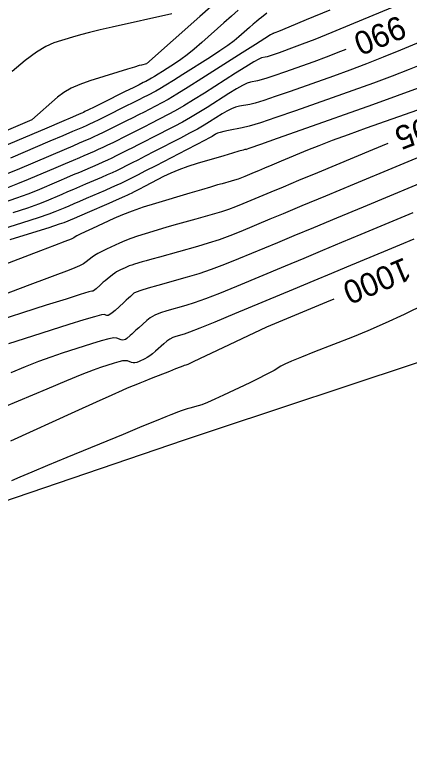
# Model space of a CAD drawing. Extents: x 2175772 to 2185556, y 721391 to 722853.
# Drawn here: x 2178722.5 to 2178770, y 721747 to 721837.5 of the extents above; entities that cross this region are included whole.
import ezdxf

# ---------------------------------------------------------------- set-up
doc = ezdxf.new("R2010")
doc.units = 0
for name, color, linetype in [('DT_X_Contour_Major', 7, 'Continuous'), ('DT_X_Contour_Minor', 7, 'Continuous'), ('DT_X_TIN_Hull', 7, 'Continuous'), ('SV_X_Break_Lines', 7, 'Continuous')]:
    doc.layers.add(name, color=color, linetype=linetype)

msp = doc.modelspace()

# ---------------------------------------------------------------- linework, layer by layer
at = {"layer": 'DT_X_Contour_Major'}
for points in [[(2178746.032, 721838.529), (2178744.732, 721837.385), (2178738.312, 721831.671), (2178737.684, 721831.532), (2178737.408, 721831.456), (2178736.847, 721831.288), (2178736.001, 721831.029), (2178734.872, 721830.678), (2178731.481, 721829.619), (2178730.285, 721829.199), (2178729.24, 721828.732), (2178728.348, 721828.218), (2178727.607, 721827.658), (2178724.501, 721824.937), (2178718.004, 721822.167)], [(2178762.304, 721833.408), (2178761.656, 721833.148), (2178759.901, 721832.468), (2178758.437, 721831.93), (2178754.921, 721830.685), (2178753.729, 721830.269), (2178752.787, 721829.955), (2178752.097, 721829.743), (2178751.659, 721829.633), (2178750.823, 721829.475), (2178750.426, 721829.345), (2178749.859, 721829.072), (2178749.124, 721828.657), (2178748.22, 721828.099), (2178745.584, 721826.422), (2178744.596, 721825.808), (2178743.61, 721825.225), (2178742.626, 721824.673), (2178741.643, 721824.151), (2178739.024, 721822.801), (2178738.101, 721822.326), (2178737.295, 721821.914), (2178736.606, 721821.564), (2178736.035, 721821.277), (2178734.668, 721820.596), (2178734.145, 721820.34), (2178733.602, 721820.085), (2178733.039, 721819.829), (2178732.456, 721819.574), (2178730.875, 721818.892), (2178730.234, 721818.617), (2178729.498, 721818.302), (2178728.668, 721817.947), (2178727.742, 721817.552), (2178725.147, 721816.445), (2178724.044, 721816.004), (2178722.68, 721815.508), (2178721.057, 721814.959)], [(2178767.335, 721822.079), (2178765.507, 721821.326), (2178758.887, 721818.571), (2178756.607, 721817.621), (2178754.732, 721816.84), (2178753.261, 721816.228), (2178749.891, 721814.822), (2178749.03, 721814.477), (2178748.173, 721814.163), (2178747.321, 721813.881), (2178746.474, 721813.63), (2178744.221, 721813.002), (2178743.364, 721812.761), (2178742.482, 721812.508), (2178741.575, 721812.243), (2178740.643, 721811.967), (2178738.125, 721811.215), (2178737.224, 721810.934), (2178736.412, 721810.655), (2178735.689, 721810.379), (2178735.053, 721810.104), (2178733.477, 721809.375), (2178732.926, 721809.109), (2178732.456, 721808.859), (2178732.066, 721808.624), (2178731.757, 721808.404), (2178731.042, 721807.838), (2178730.711, 721807.616), (2178730.258, 721807.376), (2178729.681, 721807.116), (2178728.981, 721806.838), (2178726.948, 721806.071), (2178725.976, 721805.705), (2178724.582, 721805.183), (2178722.766, 721804.504), (2178720.53, 721803.669)], [(2178760.824, 721803.359), (2178759.973, 721803.004), (2178752.737, 721799.984), (2178746.039, 721796.804), (2178744.775, 721796.205), (2178743.852, 721795.773), (2178743.272, 721795.506), (2178743.033, 721795.406), (2178742.853, 721795.359), (2178742.69, 721795.302), (2178742.338, 721795.169), (2178741.796, 721794.959), (2178741.064, 721794.671), (2178738.86, 721793.802), (2178738.104, 721793.503), (2178737.49, 721793.259), (2178737.016, 721793.07), (2178736.684, 721792.935), (2178735.986, 721792.647), (2178735.395, 721792.388), (2178734.147, 721791.826), (2178732.239, 721790.962), (2178729.674, 721789.794), (2178721.955, 721786.277)]]:
    msp.add_lwpolyline(points, dxfattribs=at)
at = {"layer": 'DT_X_Contour_Minor'}
for points in [[(2178770.884, 721839.73), (2178763.209, 721836.537), (2178760.606, 721835.459), (2178758.551, 721834.62), (2178757.045, 721834.02), (2178756.089, 721833.659), (2178754.27, 721833.015), (2178753.653, 721832.799), (2178753.166, 721832.637), (2178752.809, 721832.527), (2178752.582, 721832.47), (2178752.15, 721832.389), (2178751.833, 721832.25), (2178751.205, 721831.896), (2178750.267, 721831.327), (2178749.019, 721830.541), (2178745.275, 721828.159), (2178743.949, 721827.327), (2178742.779, 721826.618), (2178741.764, 721826.031), (2178740.904, 721825.567), (2178738.82, 721824.492), (2178738.055, 721824.099), (2178737.324, 721823.726), (2178736.626, 721823.374), (2178735.963, 721823.041), (2178734.238, 721822.182), (2178733.615, 721821.875), (2178733.037, 721821.598), (2178732.505, 721821.353), (2178732.019, 721821.138), (2178730.784, 721820.606), (2178730.224, 721820.365), (2178729.47, 721820.043), (2178728.523, 721819.638), (2178727.382, 721819.151), (2178724.08, 721817.744), (2178722.789, 721817.217), (2178721.391, 721816.692)], [(2178749.324, 721838.112), (2178748.516, 721837.418), (2178747.589, 721836.601), (2178744.958, 721834.26), (2178744.021, 721833.444), (2178743.183, 721832.755), (2178742.444, 721832.191), (2178741.805, 721831.753), (2178740.231, 721830.751), (2178739.692, 721830.411), (2178739.255, 721830.141), (2178738.921, 721829.942), (2178738.689, 721829.813), (2178738.206, 721829.564), (2178737.916, 721829.417), (2178737.41, 721829.163), (2178736.687, 721828.801), (2178735.746, 721828.332), (2178732.95, 721826.938), (2178732.023, 721826.477), (2178731.34, 721826.139), (2178730.901, 721825.923), (2178730.706, 721825.83), (2178730.511, 721825.746), (2178730.193, 721825.61), (2178729.385, 721825.266), (2178728.088, 721824.712), (2178726.3, 721823.95), (2178720.88, 721821.64)], [(2178760.379, 721838.144), (2178757.509, 721836.95), (2178755.446, 721836.093), (2178754.19, 721835.572), (2178753.741, 721835.388), (2178753.619, 721835.344), (2178753.577, 721835.33), (2178753.545, 721835.319), (2178753.521, 721835.312), (2178753.506, 721835.308), (2178753.476, 721835.302), (2178753.24, 721835.156), (2178752.551, 721834.72), (2178751.41, 721833.996), (2178749.817, 721832.983), (2178744.967, 721829.897), (2178743.302, 721828.847), (2178741.948, 721828.011), (2178740.902, 721827.389), (2178740.166, 721826.982), (2178738.615, 721826.183), (2178738.009, 721825.872), (2178737.353, 721825.538), (2178736.646, 721825.183), (2178735.891, 721824.805), (2178733.809, 721823.767), (2178733.084, 721823.409), (2178732.471, 721823.112), (2178731.97, 721822.876), (2178731.581, 721822.702), (2178730.693, 721822.319), (2178730.214, 721822.114), (2178729.442, 721821.784), (2178728.378, 721821.329), (2178723.014, 721819.043), (2178721.534, 721818.431)], [(2178752.788, 721837.751), (2178752.133, 721837.254), (2178751.859, 721837.038), (2178751.527, 721836.763), (2178751.139, 721836.429), (2178750.692, 721836.036), (2178749.426, 721834.909), (2178748.855, 721834.441), (2178748.092, 721833.88), (2178747.137, 721833.227), (2178745.99, 721832.482), (2178742.676, 721830.373), (2178741.54, 721829.656), (2178740.621, 721829.088), (2178739.916, 721828.669), (2178739.427, 721828.398), (2178738.411, 721827.874), (2178737.963, 721827.645), (2178737.381, 721827.351), (2178736.667, 721826.992), (2178735.819, 721826.569), (2178733.379, 721825.353), (2178732.553, 721824.943), (2178731.906, 721824.625), (2178731.436, 721824.4), (2178731.144, 721824.266), (2178730.602, 721824.033), (2178730.203, 721823.862), (2178729.414, 721823.525), (2178728.233, 721823.021), (2178726.661, 721822.351), (2178721.947, 721820.341)], [(2178741.339, 721837.692), (2178734.175, 721836.1), (2178732.726, 721835.768), (2178731.45, 721835.456), (2178730.345, 721835.163), (2178729.412, 721834.889), (2178727.154, 721834.184), (2178726.207, 721833.772), (2178725.059, 721833.064), (2178723.709, 721832.06), (2178722.158, 721830.76)], [(2178774.438, 721835.641), (2178768.87, 721833.325), (2178766.798, 721832.478), (2178764.76, 721831.675), (2178762.756, 721830.916), (2178760.785, 721830.202), (2178755.573, 721828.355), (2178753.804, 721827.738), (2178752.409, 721827.273), (2178751.386, 721826.958), (2178750.735, 721826.795), (2178749.497, 721826.562), (2178749.019, 721826.44), (2178748.514, 721826.248), (2178747.981, 721825.988), (2178747.422, 721825.657), (2178745.893, 721824.684), (2178745.243, 721824.289), (2178744.442, 721823.832), (2178743.488, 721823.315), (2178742.382, 721822.736), (2178739.229, 721821.11), (2178738.147, 721820.553), (2178737.266, 721820.101), (2178736.586, 721819.755), (2178736.107, 721819.514), (2178735.097, 721819.01), (2178734.676, 721818.806), (2178734.168, 721818.572), (2178733.574, 721818.306), (2178732.894, 721818.01), (2178730.966, 721817.179), (2178730.244, 721816.869), (2178729.527, 721816.561), (2178728.813, 721816.255), (2178728.103, 721815.952), (2178726.214, 721815.147), (2178725.298, 721814.79), (2178723.97, 721814.324), (2178722.227, 721813.749)], [(2178771.7, 721831.718), (2178769.895, 721830.987), (2178767.865, 721830.203), (2178765.611, 721829.365), (2178763.132, 721828.473), (2178756.224, 721826.025), (2178753.88, 721825.208), (2178752.03, 721824.59), (2178750.674, 721824.174), (2178749.812, 721823.958), (2178748.17, 721823.648), (2178747.612, 721823.535), (2178747.168, 721823.424), (2178746.839, 721823.318), (2178746.623, 721823.215), (2178746.201, 721822.947), (2178745.89, 721822.77), (2178745.273, 721822.44), (2178744.35, 721821.956), (2178743.12, 721821.32), (2178739.433, 721819.419), (2178738.193, 721818.78), (2178737.237, 721818.289), (2178736.566, 721817.946), (2178736.179, 721817.75), (2178735.527, 721817.425), (2178735.206, 721817.272), (2178734.734, 721817.058), (2178734.109, 721816.783), (2178733.332, 721816.446), (2178731.057, 721815.466), (2178730.255, 721815.12), (2178729.555, 721814.82), (2178728.958, 721814.564), (2178728.463, 721814.352), (2178727.28, 721813.848), (2178726.553, 721813.577), (2178725.259, 721813.14), (2178723.398, 721812.539), (2178720.97, 721811.774)], [(2178770.97, 721828.73), (2178768.466, 721827.813), (2178765.48, 721826.745), (2178756.875, 721823.696), (2178754.044, 721822.694), (2178752.003, 721821.974), (2178750.753, 721821.538), (2178750.293, 721821.385), (2178750.123, 721821.353), (2178749.918, 721821.298), (2178749.43, 721821.157), (2178748.659, 721820.93), (2178747.605, 721820.618), (2178744.419, 721819.671), (2178743.269, 721819.307), (2178742.21, 721818.924), (2178741.241, 721818.522), (2178740.362, 721818.102), (2178738.139, 721816.956), (2178737.396, 721816.573), (2178736.834, 721816.284), (2178736.452, 721816.088), (2178736.251, 721815.986), (2178735.957, 721815.839), (2178735.737, 721815.738), (2178735.299, 721815.545), (2178734.643, 721815.259), (2178733.769, 721814.882), (2178731.147, 721813.752), (2178729.583, 721813.079), (2178729.103, 721812.872), (2178728.824, 721812.753), (2178728.347, 721812.55), (2178727.809, 721812.363), (2178726.551, 721811.957), (2178724.574, 721811.331), (2178721.879, 721810.486)], [(2178770.915, 721826.11), (2178764.728, 721823.918), (2178762.549, 721823.136), (2178760.649, 721822.435), (2178759.029, 721821.815), (2178757.69, 721821.275), (2178754.491, 721819.944), (2178753.39, 721819.485), (2178752.483, 721819.108), (2178751.773, 721818.812), (2178751.257, 721818.597), (2178750.144, 721818.132), (2178749.728, 721817.966), (2178749.314, 721817.814), (2178748.902, 721817.678), (2178748.493, 721817.556), (2178747.405, 721817.253), (2178746.855, 721817.096), (2178746.021, 721816.852), (2178744.903, 721816.521), (2178743.502, 721816.104), (2178739.386, 721814.875), (2178737.915, 721814.416), (2178736.588, 721813.96), (2178735.406, 721813.508), (2178734.367, 721813.06), (2178731.791, 721811.869), (2178730.937, 721811.471), (2178730.309, 721811.173), (2178729.905, 721810.973), (2178729.727, 721810.871), (2178729.551, 721810.732), (2178729.252, 721810.595), (2178728.484, 721810.289), (2178727.249, 721809.813), (2178725.547, 721809.167), (2178720.383, 721807.218)], [(2178773.324, 721821.377), (2178763.283, 721817.197), (2178759.825, 721815.758), (2178756.98, 721814.573), (2178754.749, 721813.644), (2178753.132, 721812.969), (2178749.638, 721811.511), (2178748.331, 721810.988), (2178747.032, 721810.512), (2178745.74, 721810.084), (2178744.455, 721809.703), (2178739.874, 721808.425), (2178738.943, 721808.163), (2178738.247, 721807.965), (2178737.784, 721807.83), (2178736.863, 721807.555), (2178736.534, 721807.452), (2178736.237, 721807.35), (2178735.972, 721807.249), (2178735.739, 721807.148), (2178735.162, 721806.882), (2178734.942, 721806.77), (2178734.714, 721806.633), (2178734.477, 721806.473), (2178734.232, 721806.288), (2178733.569, 721805.764), (2178733.329, 721805.572), (2178733.106, 721805.388), (2178732.901, 721805.212), (2178732.712, 721805.045), (2178732.231, 721804.61), (2178732.07, 721804.469), (2178731.946, 721804.371), (2178731.86, 721804.317), (2178731.812, 721804.306), (2178731.733, 721804.334), (2178731.368, 721804.235), (2178730.331, 721803.917), (2178728.623, 721803.378), (2178726.243, 721802.62), (2178719.001, 721800.306)], [(2178773.398, 721818.204), (2178764.361, 721814.443), (2178761.176, 721813.117), (2178758.399, 721811.96), (2178756.03, 721810.973), (2178754.07, 721810.155), (2178749.385, 721808.2), (2178747.682, 721807.512), (2178746.085, 721806.915), (2178744.595, 721806.408), (2178743.211, 721805.992), (2178739.664, 721805.004), (2178738.487, 721804.667), (2178737.615, 721804.398), (2178737.05, 721804.197), (2178736.789, 721804.065), (2178736.503, 721803.801), (2178736.362, 721803.672), (2178736.153, 721803.481), (2178735.875, 721803.23), (2178735.529, 721802.917), (2178734.516, 721802), (2178734.169, 721801.704), (2178733.889, 721801.505), (2178733.676, 721801.402), (2178733.529, 721801.395), (2178733.226, 721801.506), (2178732.875, 721801.462), (2178732.048, 721801.246), (2178730.745, 721800.859), (2178728.966, 721800.3), (2178723.588, 721798.582), (2178721.703, 721797.967)], [(2178770.356, 721813.735), (2178764.103, 721811.132), (2178761.776, 721810.163), (2178759.484, 721809.209), (2178757.228, 721808.268), (2178755.007, 721807.341), (2178749.132, 721804.889), (2178747.098, 721804.055), (2178745.402, 721803.392), (2178744.045, 721802.899), (2178743.025, 721802.576), (2178740.758, 721801.945), (2178739.969, 721801.696), (2178739.303, 721801.423), (2178738.758, 721801.127), (2178738.337, 721800.806), (2178737.374, 721799.921), (2178737.04, 721799.613), (2178736.757, 721799.354), (2178736.527, 721799.143), (2178736.349, 721798.982), (2178735.945, 721798.616), (2178735.787, 721798.504), (2178735.618, 721798.446), (2178735.438, 721798.439), (2178735.246, 721798.485), (2178734.719, 721798.678), (2178734.382, 721798.688), (2178733.764, 721798.576), (2178732.867, 721798.34), (2178731.689, 721797.98), (2178728.175, 721796.857), (2178726.799, 721796.395), (2178725.305, 721795.85), (2178723.694, 721795.222), (2178721.965, 721794.511)], [(2178770.46, 721810.576), (2178768.751, 721809.864), (2178767.314, 721809.266), (2178762.376, 721807.21), (2178760.569, 721806.457), (2178758.425, 721805.563), (2178755.944, 721804.527), (2178748.879, 721801.579), (2178746.514, 721800.598), (2178744.719, 721799.868), (2178743.494, 721799.389), (2178742.839, 721799.161), (2178741.852, 721798.886), (2178741.482, 721798.753), (2178741.113, 721798.561), (2178740.743, 721798.31), (2178740.374, 721798), (2178739.39, 721797.094), (2178739.034, 721796.781), (2178738.703, 721796.523), (2178738.398, 721796.32), (2178738.119, 721796.172), (2178737.408, 721795.85), (2178737.152, 721795.752), (2178736.916, 721795.702), (2178736.701, 721795.698), (2178736.507, 721795.742), (2178736.017, 721795.921), (2178735.779, 721795.955), (2178735.432, 721795.923), (2178734.976, 721795.825), (2178734.412, 721795.66), (2178732.762, 721795.133), (2178731.896, 721794.823), (2178730.533, 721794.289), (2178728.673, 721793.53), (2178726.317, 721792.546), (2178719.373, 721789.623)], [(2178771.824, 721802.763), (2178769.303, 721801.532), (2178767.01, 721800.461), (2178764.944, 721799.55), (2178763.105, 721798.797), (2178758.505, 721797.003), (2178756.958, 721796.391), (2178755.769, 721795.901), (2178754.936, 721795.533), (2178754.461, 721795.287), (2178753.671, 721794.793), (2178753.264, 721794.561), (2178752.638, 721794.236), (2178751.791, 721793.817), (2178750.724, 721793.305), (2178747.585, 721791.815), (2178746.51, 721791.314), (2178745.638, 721790.93), (2178744.97, 721790.661), (2178744.505, 721790.508), (2178743.537, 721790.256), (2178743.177, 721790.157), (2178742.823, 721790.048), (2178742.476, 721789.929), (2178742.134, 721789.8), (2178741.233, 721789.445), (2178740.62, 721789.198), (2178739.458, 721788.723), (2178737.746, 721788.02), (2178735.484, 721787.089), (2178728.719, 721784.304), (2178726.4, 721783.345), (2178724.518, 721782.557), (2178723.073, 721781.94), (2178722.065, 721781.495)]]:
    msp.add_lwpolyline(points, dxfattribs=at)
at = {"layer": 'DT_X_TIN_Hull'}
msp.add_lwpolyline([(2178623.731, 721746.955), (2178647.535, 721754.586), (2178648.95, 721755.04), (2178672.703, 721762.834), (2178695.543, 721770.328), (2178719.209, 721778.379), (2178742.875, 721786.431), (2178746.708, 721787.735), (2178770.443, 721795.584), (2178794.178, 721803.433), (2178795.878, 721803.995), (2178819.557, 721812.012), (2178837.71, 721818.159), (2178861.405, 721826.129), (2178885.1, 721834.1), (2178908.796, 721842.07), (2178932.491, 721850.041), (2178956.186, 721858.011), (2178979.881, 721865.982), (2179003.576, 721873.952)], dxfattribs=at)
at = {"layer": 'SV_X_Break_Lines'}
msp.add_line((2178750.381, 721821.228), (2178750.381, 721821.228), dxfattribs=at)

# ---------------------------------------------------------------- texts
at = {"layer": 'DT_X_Contour_Major'}
for s, rotation, p in [('990', 202.39432, (2178768.758, 721837.566)), ('995', 200.81082, (2178773.759, 721826.088)), ('1000', 202.63973, (2178769.359, 721808.435))]:
    msp.add_text(s, height=2.8, rotation=rotation, dxfattribs=at).set_placement(p)

doc.saveas('drawing.dxf')
